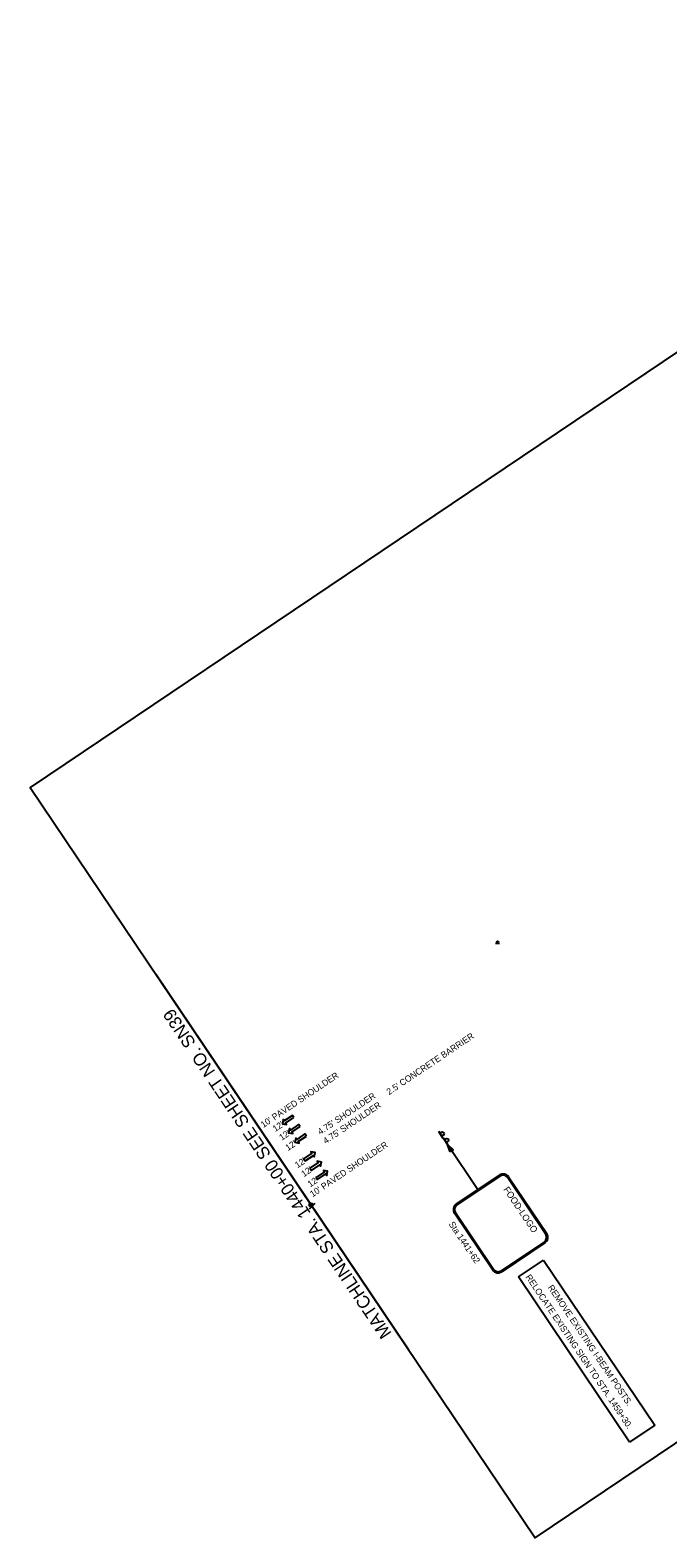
# Model space of a CAD drawing. Extents: x 1791953 to 1793697, y 1184916 to 1186619.
# Drawn here: x 1791953 to 1792658, y 1184916 to 1186583 of the extents above; entities that cross this region are included whole.
import ezdxf

# ---------------------------------------------------------------- set-up
doc = ezdxf.new("R2010")
doc.units = 0
for name, color, linetype in [('RD_DTM_BkLn2', 7, 'Continuous'), ('RD_EX_DR_Inlet_txCode', 7, 'Continuous'), ('RD_EX_Driveway', 7, 'Continuous'), ('RD_EX_Fence_ChLk', 7, 'Continuous'), ('RD_EX_H2O', 7, 'Continuous')]:
    doc.layers.add(name, color=color, linetype=linetype)

# ---------------------------------------------------------------- blocks, each defined once
blk = doc.blocks.new('SARRW2')
at = {"layer": 'RD_EX_H2O'}
blk.add_lwpolyline([(-12, 1.2), (-12, -1.2), (-2.8, -1.2), (-2.8, -2.8), (0, 0), (-2.8, 2.8), (-2.8, 1.2)], close=True, dxfattribs=at)

msp = doc.modelspace()

# ---------------------------------------------------------------- linework, layer by layer
at = {"layer": 'RD_DTM_BkLn2'}
msp.add_lwpolyline([(1792371.8, 1185122.9), (1792232.2, 1185330.3), (1792092.6, 1185537.7)], dxfattribs=at)
at = {"layer": 'RD_EX_DR_Inlet_txCode'}
msp.add_lwpolyline([(1793089.7, 1185304.8), (1793031, 1185391.9), (1793697.1, 1185840.3), (1793197.3, 1186582.7), (1793197.3, 1186582.7), (1791953, 1185745.1), (1792511.4, 1184915.5)], close=True, dxfattribs=at)
at = {"layer": 'RD_EX_Fence_ChLk'}
for p, q in [((1792467.6, 1185573.3), (1792472.1, 1185573.3)), ((1792404.4, 1185365.1), (1792409.4, 1185357.6)), ((1792409.5, 1185357.9), (1792414.5, 1185350.4)), ((1792448.1, 1185300.5), (1792414.5, 1185350.4)), ((1792261.8, 1185279.2), (1792268.1, 1185285.6)), ((1792492.8, 1185204), (1792520.7, 1185222.7)), ((1792520.7, 1185222.7), (1792643.6, 1185040.2)), ((1792615.7, 1185021.5), (1792492.8, 1185204)), ((1792643.6, 1185040.2), (1792615.7, 1185021.5))]:
    msp.add_line(p, q, dxfattribs=at)
msp.add_lwpolyline([(1792417.4, 1185342.4), (1792414.5, 1185350.4), (1792420.8, 1185344.7)], close=True, dxfattribs=at)
for points in [[(1792424.2, 1185284.4), (1792472, 1185316.6)], [(1792424.8, 1185283.4), (1792472.6, 1185315.6)], [(1792481, 1185314), (1792523.2, 1185251.3)], [(1792482, 1185314.7), (1792524.2, 1185251.9)], [(1792464.4, 1185211.7), (1792422.2, 1185274.4)], [(1792465.4, 1185212.4), (1792423.2, 1185275.1)], [(1792521.6, 1185242.9), (1792473.8, 1185210.8)], [(1792522.2, 1185241.9), (1792474.4, 1185209.8)]]:
    msp.add_lwpolyline(points, dxfattribs=at)
for centre, radius in [((1792469.9, 1185574.3), 1), ((1792408.6, 1185362.4), 2), ((1792413.7, 1185355.2), 2), ((1792263.5, 1185283.8), 2)]:
    msp.add_circle(centre, radius, dxfattribs=at)
for centre, radius, start, end in [((1792476, 1185310.6), 7.2, 33.9476, 123.9476), ((1792476, 1185310.6), 6, 33.9476, 123.9476), ((1792428.2, 1185278.5), 7.2, 123.9476, 213.9476), ((1792428.2, 1185278.5), 6, 123.9476, 213.9476), ((1792518.2, 1185247.9), 6, 303.9476, 33.9476), ((1792518.2, 1185247.9), 7.2, 303.9476, 33.9476), ((1792470.4, 1185215.8), 7.2, 213.9476, 303.9476), ((1792470.4, 1185215.8), 6, 213.9476, 303.9476)]:
    msp.add_arc(centre, radius, start, end, dxfattribs=at)

# ---------------------------------------------------------------- block references
at = {"layer": 'RD_EX_H2O', "xscale": 1.1999999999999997}
for p, yscale, rotation in [((1792231.9, 1185373.5), 1.2000000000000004, -146.05256015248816), ((1792238.7, 1185363.4), 1.2000000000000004, -146.05256015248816), ((1792245.7, 1185353), 1.2000000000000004, -146.05256015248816), ((1792268.1, 1185341.5), 1.2, 33.94743984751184), ((1792275.1, 1185331.1), 1.2, 33.94743984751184), ((1792281.9, 1185321), 1.2, 33.94743984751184)]:
    msp.add_blockref('SARRW2', p, dxfattribs=dict(at, yscale=yscale, rotation=rotation))

# ---------------------------------------------------------------- texts
at = {"layer": 'RD_DTM_BkLn2'}
msp.add_text('MATCHLINE STA. 1440+00 SEE SHEET NO. SN39', height=14, rotation=123.9476, dxfattribs=at).set_placement((1792353.2, 1185141.7))
at = {"layer": 'RD_EX_Driveway'}
for s, p in [("2.5' CONCRETE BARRIER", (1792349.9, 1185405)), ("10' PAVED SHOULDER", (1792210.9, 1185368.7)), ("4.75' SHOULDER", (1792273.8, 1185360.9)), ("4.75' SHOULDER", (1792279.8, 1185350.8)), ("12'", (1792224, 1185364.2)), ("12'", (1792231.2, 1185354.5)), ("12'", (1792238.1, 1185343.2)), ("10' PAVED SHOULDER", (1792265.3, 1185292)), ("12'", (1792248.6, 1185324)), ("12'", (1792255.7, 1185314.3)), ("12'", (1792262.7, 1185303))]:
    msp.add_text(s, height=7, rotation=33.9474, dxfattribs=at).set_placement(p)
at = {"layer": 'RD_EX_Fence_ChLk'}
for s, height, rotation, p in [('FOOD-LOGO', 7.2, 303.9476, (1792475.9, 1185300.8)), ('Sta 1441+62', 7, 303.9477, (1792415.4, 1185262.4)), ('RELOCATE EXISTING SIGN TO STA. 1459+30.', 7, 303.9477, (1792500.4, 1185203.9)), ('REMOVE EXISTING I-BEAM POSTS.', 7, 303.9477, (1792525, 1185192.4))]:
    msp.add_text(s, height=height, rotation=rotation, dxfattribs=at).set_placement(p)

doc.saveas('drawing.dxf')
